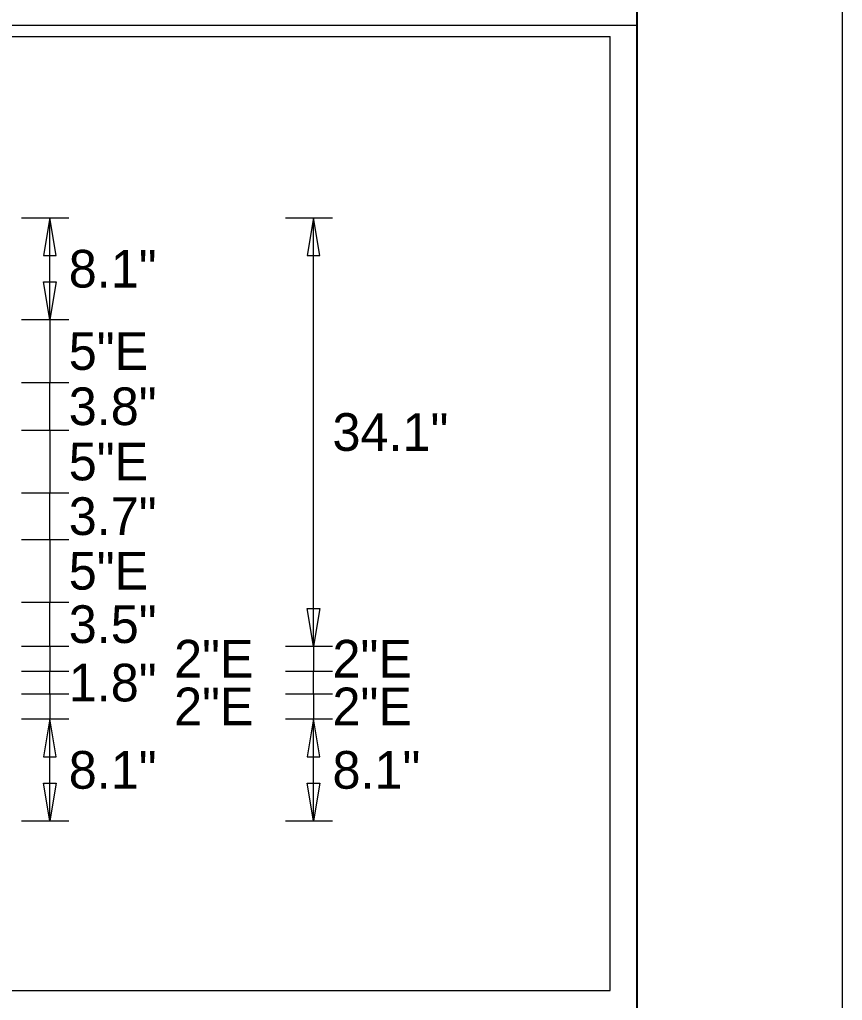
# Model space of a CAD drawing. Extents: x 17890628 to 17890844, y 17897693 to 17898031.
# Drawn here: x 17890824.88 to 17890843.99, y 17897934.73 to 17897957.5 of the extents above; entities that cross this region are included whole.
import ezdxf

# ---------------------------------------------------------------- set-up
doc = ezdxf.new("R2010")
doc.units = 0
for name, color, linetype in [('GSDims', 7, 'Continuous'), ('PlotBorder_dp', 7, 'Continuous'), ('SheetBorder_dp', 7, 'Continuous'), ('SheetLinesMisc2_dp', 7, 'Continuous')]:
    doc.layers.add(name, color=color, linetype=linetype)

msp = doc.modelspace()

# ---------------------------------------------------------------- linework, layer by layer
at = {"layer": 'GSDims'}
for p, q in [((17890824.928, 17897952.897), (17890826.022, 17897952.897)), ((17890825.584, 17897950.535), (17890825.584, 17897952.897)), ((17890831.053, 17897952.897), (17890832.147, 17897952.897)), ((17890831.709, 17897942.952), (17890831.709, 17897952.897)), ((17890824.928, 17897950.535), (17890826.022, 17897950.535)), ((17890824.928, 17897950.535), (17890826.022, 17897950.535)), ((17890825.584, 17897950.535), (17890825.584, 17897949.077)), ((17890824.928, 17897949.077), (17890826.022, 17897949.077)), ((17890824.928, 17897949.077), (17890826.022, 17897949.077)), ((17890825.584, 17897947.968), (17890825.584, 17897949.077)), ((17890824.928, 17897947.968), (17890826.022, 17897947.968)), ((17890824.928, 17897947.968), (17890826.022, 17897947.968)), ((17890825.584, 17897947.968), (17890825.584, 17897946.51)), ((17890824.928, 17897946.51), (17890826.022, 17897946.51)), ((17890824.928, 17897946.51), (17890826.022, 17897946.51)), ((17890825.584, 17897945.431), (17890825.584, 17897946.51)), ((17890824.928, 17897945.431), (17890826.022, 17897945.431)), ((17890824.928, 17897945.431), (17890826.022, 17897945.431)), ((17890825.584, 17897945.431), (17890825.584, 17897943.972)), ((17890824.928, 17897943.972), (17890826.022, 17897943.972)), ((17890824.928, 17897943.972), (17890826.022, 17897943.972)), ((17890825.584, 17897942.952), (17890825.584, 17897943.972)), ((17890824.928, 17897942.952), (17890826.022, 17897942.952)), ((17890824.928, 17897942.952), (17890826.022, 17897942.952)), ((17890825.584, 17897942.952), (17890825.584, 17897942.368)), ((17890831.053, 17897942.952), (17890832.147, 17897942.952)), ((17890831.053, 17897942.952), (17890832.147, 17897942.952)), ((17890831.709, 17897942.952), (17890831.709, 17897942.368)), ((17890824.928, 17897942.368), (17890826.022, 17897942.368)), ((17890824.928, 17897942.368), (17890826.022, 17897942.368)), ((17890825.584, 17897941.843), (17890825.584, 17897942.368)), ((17890831.053, 17897942.368), (17890832.147, 17897942.368)), ((17890831.053, 17897942.368), (17890832.147, 17897942.368)), ((17890831.709, 17897941.843), (17890831.709, 17897942.368)), ((17890824.928, 17897941.843), (17890826.022, 17897941.843)), ((17890824.928, 17897941.843), (17890826.022, 17897941.843)), ((17890825.584, 17897941.843), (17890825.584, 17897941.26)), ((17890831.053, 17897941.843), (17890832.147, 17897941.843)), ((17890831.053, 17897941.843), (17890832.147, 17897941.843)), ((17890831.709, 17897941.843), (17890831.709, 17897941.26)), ((17890824.928, 17897941.26), (17890826.022, 17897941.26)), ((17890824.928, 17897941.26), (17890826.022, 17897941.26)), ((17890825.584, 17897938.897), (17890825.584, 17897941.26)), ((17890831.053, 17897941.26), (17890832.147, 17897941.26)), ((17890831.053, 17897941.26), (17890832.147, 17897941.26)), ((17890831.709, 17897938.897), (17890831.709, 17897941.26)), ((17890824.928, 17897938.897), (17890826.022, 17897938.897)), ((17890831.053, 17897938.897), (17890832.147, 17897938.897))]:
    msp.add_line(p, q, dxfattribs=at)
for points in [[(17890825.584, 17897952.897), (17890825.438, 17897952.022), (17890825.73, 17897952.022)], [(17890831.709, 17897952.897), (17890831.563, 17897952.022), (17890831.855, 17897952.022)], [(17890825.584, 17897950.535), (17890825.438, 17897951.41), (17890825.73, 17897951.41)], [(17890831.709, 17897942.952), (17890831.563, 17897943.827), (17890831.855, 17897943.827)], [(17890825.584, 17897941.26), (17890825.438, 17897940.385), (17890825.73, 17897940.385)], [(17890831.709, 17897941.26), (17890831.563, 17897940.385), (17890831.855, 17897940.385)], [(17890825.584, 17897938.897), (17890825.438, 17897939.772), (17890825.73, 17897939.772)], [(17890831.709, 17897938.897), (17890831.563, 17897939.772), (17890831.855, 17897939.772)]]:
    msp.add_lwpolyline(points, close=True, dxfattribs=at)
at = {"layer": 'PlotBorder_dp'}
msp.add_lwpolyline([(17890700.471, 17897907.61), (17890843.989, 17897907.61), (17890843.989, 17897999.809), (17890700.471, 17897999.809)], close=True, dxfattribs=at)
at = {"layer": 'SheetBorder_dp'}
msp.add_line((17890839.205, 17897998.94), (17890839.205, 17897908.479), dxfattribs=at)
at = {"layer": 'SheetLinesMisc2_dp'}
for p, q in [((17890839.233, 17897915.484), (17890839.233, 17897998.731)), ((17890705.5, 17897957.37), (17890839.233, 17897957.37)), ((17890793.11, 17897957.108), (17890838.594, 17897957.108)), ((17890838.594, 17897934.985), (17890838.594, 17897957.109)), ((17890793.11, 17897934.953), (17890838.594, 17897934.953)), ((17890838.594, 17897934.955), (17890838.594, 17897934.985))]:
    msp.add_line(p, q, dxfattribs=at)

# ---------------------------------------------------------------- texts
at = {"layer": 'GSDims'}
for s, p in [('8.1"', (17890826.022, 17897951.279)), ('5"E', (17890826.022, 17897949.368)), ('3.8"', (17890826.022, 17897948.085)), ('34.1"', (17890832.147, 17897947.487)), ('5"E', (17890826.022, 17897946.802)), ('3.7"', (17890826.022, 17897945.533)), ('5"E', (17890826.022, 17897944.264)), ('3.5"', (17890826.022, 17897943.025)), ('2"E', (17890828.468, 17897942.222)), ('2"E', (17890832.147, 17897942.222)), ('1.8"', (17890826.022, 17897941.668)), ('2"E', (17890828.468, 17897941.114)), ('2"E', (17890832.147, 17897941.114)), ('8.1"', (17890826.022, 17897939.641)), ('8.1"', (17890832.147, 17897939.641))]:
    msp.add_text(s, height=0.875, dxfattribs=at).set_placement(p)

doc.saveas('drawing.dxf')
